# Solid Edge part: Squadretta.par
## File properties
Author: f_grande
Template: Normal.par
Last saved by: f_grande
Revision: 3
Application: Solid Edge
Material: Acciaio galvanizzato
Stile della faccia: Acciaio
Stile di riempimento: ANSI32(Acciaio)
Stile virtuale: Galvanizzato
Coef. of Thermal Exp: 0.0
Thermal Conductivity: 32.0
Specific Heat: 481.0
Modulus of Elasticity: 199947953000.0
Poisson's Ratio: 0.29
Yield Stress: 262000766.0
Ultimate Stress: 358527364.0
Elongation: 0.0
Tipo di contenuto documento: 0
Densità: 7833,000 kg/m^3
Precisione: 0,990
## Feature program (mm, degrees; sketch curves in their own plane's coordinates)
sketch for "unnamed Protrusion 1" plane through (0, 0, 0) normal (0, 0, 1) x-axis (1, 0, 0)
  line (-12.4267, 14.2464) -> (-0.4267, 14.2464)
  line (-0.4267, -3.7536) -> (-0.4267, 14.2464)
  line (17.5733, -3.7536) -> (-0.4267, -3.7536)
  line (17.5733, -15.7536) -> (17.5733, -3.7536)
  line (-12.4267, -15.7536) -> (17.5733, -15.7536)
  line (-12.4267, -15.7536) -> (-12.4267, 14.2464)
  dimension (linear) = 12.4267
  dimension (linear) = 12.4267
  dimension (linear) = 12.4267
  dimension (linear) = 17.5733
extrude "unnamed Protrusion 1" add finite 1.2 along +normal
sketch for "Foro_1" plane through (2.5733, -0.7536, 1.2) normal (0, 0, 1) x-axis (1, 0, 0)
  hole centre (-9, -9) bore radius 1.5
hole "Foro_1" diameter 3 through  CounterSinkAngle = 82 deg
sketch for "unnamed Hole 1" plane through (2.5733, -0.7536, 1.2) normal (0, 0, 1) x-axis (1, 0, 0)
  hole centre (9, -9) bore radius 1.5
hole "unnamed Hole 1" through
sketch for "unnamed Hole 2" plane through (2.5733, -0.7536, 1.2) normal (0, 0, 1) x-axis (1, 0, 0)
  hole centre (-9, 9) bore radius 1.5
hole "unnamed Hole 2" through
pattern "unnamed Pattern 1" of "Foro_1", "unnamed Hole 1", "unnamed Hole 2"
sketch for "ExtrudedCutout_1" plane through (2.5733, -0.7536, 1.2) normal (0, 0, 1) x-axis (1, 0, 0)
extrude "ExtrudedCutout_1" cut finite 49.2005 along -normal
sketch for "Foro_4" plane through (2.5733, -0.7536, 1.2) normal (0, 0, 1) x-axis (1, 0, 0)
hole "Foro_4" diameter 4.5 through
sketch for "Foro_5" plane through (2.5733, -0.7536, 1.2) normal (0, 0, 1) x-axis (1, 0, 0)
  hole centre (-9, 0) bore radius 2.25
hole "Foro_5" diameter 4.5 through
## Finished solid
Body 1: solid body, 15 faces, 36 edges, 20 vertices.
  Faces by surface: plane 10, cone 3, cylinder 2
  Edges by curve: line 26, circle 10
Bounding box of the edges (mm): 30.000 x 30.000 x 1.200, from (-12.4267, -15.7536, 0) to (17.5733, 14.2464, 1.2).
Cylindrical faces by radius (mm): R2.25 x2
Conical faces (half-angle, radius in mm at the cone's reference point): 41 deg R3 x3
Planar faces by outward normal: +x 1, +y 1, +z 1, -x 1, -y 1, -z 1, oblique 4
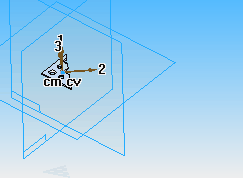
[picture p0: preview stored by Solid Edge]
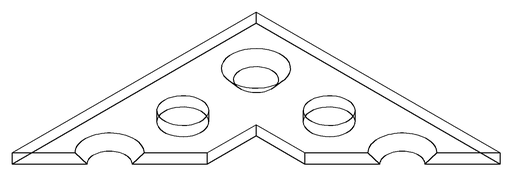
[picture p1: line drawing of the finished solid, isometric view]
